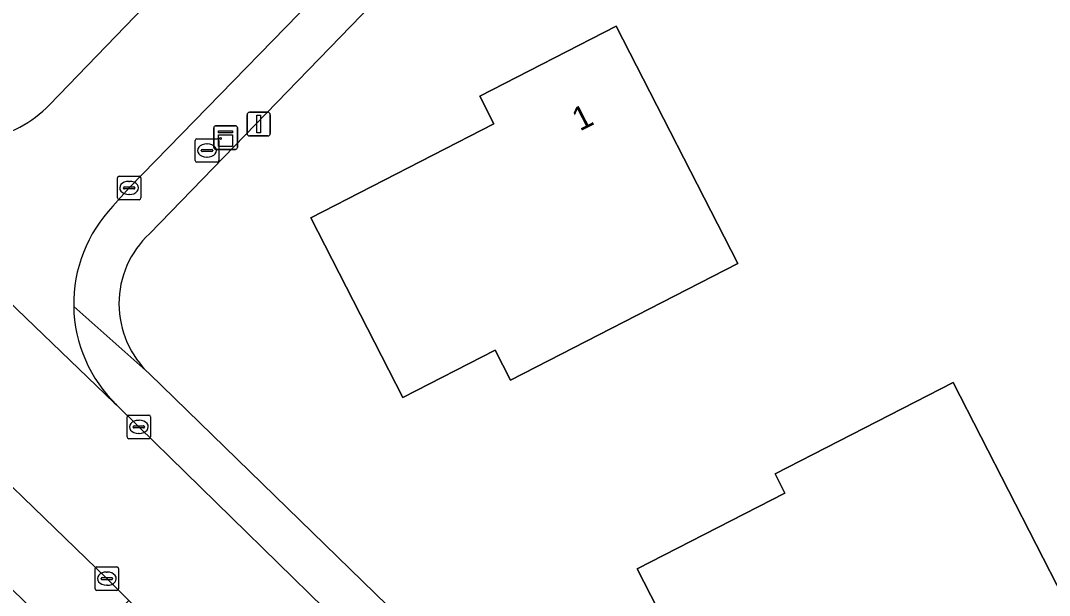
# Model space of a CAD drawing. Extents: x 162722 to 165104, y 384719 to 386284.
# Drawn here: x 163738.67 to 163782.39, y 384905.7 to 384930.12 of the extents above; entities that cross this region are included whole.
import ezdxf

# ---------------------------------------------------------------- set-up
doc = ezdxf.new("R2010")
doc.units = 0
for name, color, linetype in [('IMGEO_Brandkraan', 7, 'Continuous'), ('IMGEO_Erf', 7, 'Continuous'), ('IMGEO_Groenvoorziening', 7, 'Continuous'), ('IMGEO_Kast', 7, 'Continuous'), ('IMGEO_Kolk', 7, 'Continuous'), ('IMGEO_Lichtmast', 7, 'Continuous'), ('IMGEO_Pand', 7, 'Continuous'), ('IMGEO_Pand_nummerreeks', 7, 'Continuous'), ('IMGEO_Parkeervlak_open', 7, 'Continuous'), ('IMGEO_Rijbaan_lokaal_open', 7, 'Continuous')]:
    doc.layers.add(name, color=color, linetype=linetype)

msp = doc.modelspace()

# ---------------------------------------------------------------- linework, layer by layer
at = {"layer": 'IMGEO_Brandkraan'}
for p, q in [((163746.164, 384925.101), (163747.016, 384925.101)), ((163746.089, 384924.175), (163746.089, 384925.027)), ((163746.391, 384924.644), (163746.789, 384924.644)), ((163746.577, 384924.881), (163746.602, 384924.881)), ((163747.09, 384925.027), (163747.09, 384924.175)), ((163746.348, 384924.595), (163746.348, 384924.607)), ((163746.786, 384924.558), (163746.388, 384924.558)), ((163746.6, 384924.321), (163746.575, 384924.321)), ((163746.832, 384924.607), (163746.832, 384924.595)), ((163747.016, 384924.101), (163746.164, 384924.101))]:
    msp.add_line(p, q, dxfattribs=at)
for points in [[(163746.164, 384925.101), (163747.016, 384925.101)], [(163746.089, 384924.175), (163746.089, 384925.027)], [(163747.09, 384925.027), (163747.09, 384924.175)], [(163747.016, 384924.101), (163746.164, 384924.101)]]:
    msp.add_lwpolyline(points, dxfattribs=at)
for centre, radius, start, end in [((163746.166, 384925.025), 0.0765, 91.552, 178.448), ((163746.166, 384925.025), 0.0765, 91.552, 178.448), ((163747.014, 384925.025), 0.0765, 1.552, 88.448), ((163747.014, 384925.025), 0.0765, 1.552, 88.448), ((163746.388, 384924.604), 0.0403, 85.8775, 175.7526), ((163746.793, 384924.606), 0.0386, 1.7309, 96.639), ((163746.385, 384924.594), 0.0366, 178.938, 274.7102), ((163746.789, 384924.601), 0.043, 264.8664, 352.4533), ((163746.166, 384924.177), 0.0765, 181.552, 268.448), ((163746.166, 384924.177), 0.0765, 181.552, 268.448), ((163747.014, 384924.177), 0.0765, 271.552, 358.448), ((163747.014, 384924.177), 0.0765, 271.552, 358.448)]:
    msp.add_arc(centre, radius, start, end, dxfattribs=at)
for centre, major_axis, ratio, start_param, end_param in [((163746.576, 384924.601), (-0.387, 0.002), 0.722429, 4.712389, 7.853982), ((163746.601, 384924.601), (-0.39, 0.002), 0.717154, 1.570796, 4.712389)]:
    msp.add_ellipse(centre, major_axis=major_axis, ratio=ratio, start_param=start_param, end_param=end_param, dxfattribs=at)
at = {"layer": 'IMGEO_Erf'}
for points in [[(163773.478, 384979.9), (163782.291, 384962.358), (163782.404, 384962.416), (163802.16, 384972.581), (163804.226, 384968.418), (163784.518, 384958.283), (163775.869, 384953.781), (163770.816, 384948.556), (163767.966, 384945.654), (163759.567, 384936.98), (163755.864, 384933.157), (163744.141, 384921.063)], [(163739.897, 384926.539), (163750.364, 384937.388), (163772.76, 384960.515)], [(163744.145, 384915.113), (163756.92, 384902.682), (163761.551, 384898.186), (163768.518, 384891.364)]]:
    msp.add_lwpolyline(points, dxfattribs=at)
for points in [[(163759.487, 384914.845), (163758.837, 384916.113), (163754.916, 384914.101), (163750.999, 384921.736), (163758.783, 384925.73), (163758.18, 384926.906), (163763.981, 384929.883), (163769.153, 384919.805)], [(163785.355, 384900.981), (163777.882, 384897.15), (163774.136, 384904.459), (163767.758, 384901.19), (163764.87, 384906.825), (163771.152, 384910.045), (163770.733, 384910.863), (163778.304, 384914.744)]]:
    msp.add_lwpolyline(points, close=True, dxfattribs=at)
for centre, radius, start, end in [((163735.945, 384930.498), 5.594, 282.6076, 314.948), ((163746.913, 384918.09), 4.065, 132.9921, 227.0849)]:
    msp.add_arc(centre, radius, start, end, dxfattribs=at)
at = {"layer": 'IMGEO_Groenvoorziening'}
msp.add_lwpolyline([(163743.27, 384905.487), (163742.334, 384906.411), (163734.773, 384913.719), (163730.72, 384917.677), (163728.529, 384915.354), (163741.103, 384903.254)], close=True, dxfattribs=at)
at = {"layer": 'IMGEO_Kast'}
for p, q in [((163746.88, 384924.723), (163746.88, 384925.564)), ((163746.88, 384925.564), (163746.88, 384924.723)), ((163746.955, 384925.648), (163747.796, 384925.648)), ((163747.796, 384925.648), (163746.955, 384925.648)), ((163747.88, 384925.573), (163747.88, 384924.732)), ((163747.88, 384924.732), (163747.88, 384925.573)), ((163747.805, 384924.648), (163746.964, 384924.648)), ((163746.964, 384924.648), (163747.805, 384924.648))]:
    msp.add_line(p, q, dxfattribs=at)
for points in [[(163747.075, 384925.438), (163747.675, 384925.438), (163747.675, 384925.353), (163747.075, 384925.353), (163747.075, 384925.438)], [(163747.075, 384925.263), (163747.675, 384925.263), (163747.675, 384924.774), (163747.075, 384924.774), (163747.075, 384925.263)]]:
    msp.add_lwpolyline(points, dxfattribs=at)
msp.add_circle((163747.159, 384925.112), 0.0377, dxfattribs=at)
for centre, start, end in [((163746.958, 384925.57), 92.4484, 184.2845), ((163746.958, 384925.57), 92.4484, 184.2845), ((163747.802, 384925.57), 2.4484, 94.2845), ((163747.802, 384925.57), 2.4484, 94.2845), ((163746.958, 384924.726), 182.4484, 274.2845), ((163746.958, 384924.726), 182.4484, 274.2845), ((163747.802, 384924.726), 272.4484, 4.2845), ((163747.802, 384924.726), 272.4484, 4.2845)]:
    msp.add_arc(centre, 0.0779, start, end, dxfattribs=at)
at = {"layer": 'IMGEO_Kolk'}
for p, q in [((163742.779, 384922.585), (163742.779, 384923.437)), ((163742.854, 384923.511), (163743.706, 384923.511)), ((163743.78, 384923.437), (163743.78, 384922.585)), ((163743.038, 384923.005), (163743.038, 384923.017)), ((163743.476, 384922.968), (163743.078, 384922.968)), ((163743.081, 384923.054), (163743.479, 384923.054)), ((163743.267, 384923.291), (163743.292, 384923.291)), ((163743.522, 384923.017), (163743.522, 384923.005)), ((163743.706, 384922.511), (163742.854, 384922.511)), ((163743.29, 384922.731), (163743.265, 384922.731)), ((163743.193, 384912.432), (163743.193, 384913.284)), ((163743.268, 384913.358), (163744.12, 384913.358)), ((163744.194, 384913.284), (163744.194, 384912.432)), ((163743.452, 384912.852), (163743.452, 384912.864)), ((163743.495, 384912.901), (163743.893, 384912.901)), ((163743.681, 384913.138), (163743.706, 384913.138)), ((163743.936, 384912.864), (163743.936, 384912.852)), ((163743.89, 384912.815), (163743.492, 384912.815)), ((163743.704, 384912.578), (163743.679, 384912.578)), ((163744.12, 384912.358), (163743.268, 384912.358)), ((163741.833, 384905.985), (163741.833, 384906.837)), ((163741.908, 384906.911), (163742.76, 384906.911)), ((163742.834, 384906.837), (163742.834, 384905.985)), ((163742.092, 384906.405), (163742.092, 384906.417)), ((163742.53, 384906.368), (163742.132, 384906.368)), ((163742.135, 384906.454), (163742.533, 384906.454)), ((163742.321, 384906.691), (163742.346, 384906.691)), ((163742.576, 384906.417), (163742.576, 384906.405)), ((163742.76, 384905.911), (163741.908, 384905.911)), ((163742.344, 384906.131), (163742.319, 384906.131))]:
    msp.add_line(p, q, dxfattribs=at)
for points in [[(163742.779, 384922.585), (163742.779, 384923.437)], [(163742.854, 384923.511), (163743.706, 384923.511)], [(163743.78, 384923.437), (163743.78, 384922.585)], [(163743.706, 384922.511), (163742.854, 384922.511)], [(163743.193, 384912.432), (163743.193, 384913.284)], [(163743.268, 384913.358), (163744.12, 384913.358)], [(163744.194, 384913.284), (163744.194, 384912.432)], [(163744.12, 384912.358), (163743.268, 384912.358)], [(163741.833, 384905.985), (163741.833, 384906.837)], [(163741.908, 384906.911), (163742.76, 384906.911)], [(163742.834, 384906.837), (163742.834, 384905.985)], [(163742.76, 384905.911), (163741.908, 384905.911)]]:
    msp.add_lwpolyline(points, dxfattribs=at)
for centre, radius, start, end in [((163742.856, 384923.435), 0.0765, 91.552, 178.448), ((163742.856, 384923.435), 0.0765, 91.552, 178.448), ((163743.704, 384923.435), 0.0765, 1.552, 88.448), ((163743.704, 384923.435), 0.0765, 1.552, 88.448), ((163743.078, 384923.014), 0.0403, 85.8775, 175.7526), ((163743.075, 384923.004), 0.0366, 178.938, 274.7102), ((163743.479, 384923.011), 0.043, 264.8664, 352.4533), ((163743.483, 384923.016), 0.0386, 1.7309, 96.639), ((163742.856, 384922.587), 0.0765, 181.552, 268.448), ((163742.856, 384922.587), 0.0765, 181.552, 268.448), ((163743.704, 384922.587), 0.0765, 271.552, 358.448), ((163743.704, 384922.587), 0.0765, 271.552, 358.448), ((163743.27, 384913.282), 0.0765, 91.552, 178.448), ((163743.27, 384913.282), 0.0765, 91.552, 178.448), ((163744.118, 384913.282), 0.0765, 1.552, 88.448), ((163744.118, 384913.282), 0.0765, 1.552, 88.448), ((163743.492, 384912.861), 0.0403, 85.8775, 175.7526), ((163743.489, 384912.851), 0.0366, 178.938, 274.7102), ((163743.893, 384912.858), 0.043, 264.8664, 352.4533), ((163743.897, 384912.863), 0.0386, 1.7309, 96.639), ((163743.27, 384912.434), 0.0765, 181.552, 268.448), ((163743.27, 384912.434), 0.0765, 181.552, 268.448), ((163744.118, 384912.434), 0.0765, 271.552, 358.448), ((163744.118, 384912.434), 0.0765, 271.552, 358.448), ((163741.91, 384906.835), 0.0765, 91.552, 178.448), ((163741.91, 384906.835), 0.0765, 91.552, 178.448), ((163742.758, 384906.835), 0.0765, 1.552, 88.448), ((163742.758, 384906.835), 0.0765, 1.552, 88.448), ((163742.132, 384906.414), 0.0403, 85.8775, 175.7526), ((163742.129, 384906.404), 0.0366, 178.938, 274.7102), ((163742.533, 384906.411), 0.043, 264.8664, 352.4533), ((163742.537, 384906.416), 0.0386, 1.7309, 96.639), ((163741.91, 384905.987), 0.0765, 181.552, 268.448), ((163741.91, 384905.987), 0.0765, 181.552, 268.448), ((163742.758, 384905.987), 0.0765, 271.552, 358.448), ((163742.758, 384905.987), 0.0765, 271.552, 358.448)]:
    msp.add_arc(centre, radius, start, end, dxfattribs=at)
for centre, major_axis, ratio, start_param, end_param in [((163743.266, 384923.011), (-0.387, 0.002), 0.722429, 4.712389, 7.853982), ((163743.291, 384923.011), (-0.39, 0.002), 0.717154, 1.570796, 4.712389), ((163743.68, 384912.858), (-0.387, 0.002), 0.722429, 4.712389, 7.853982), ((163743.705, 384912.858), (-0.39, 0.002), 0.717154, 1.570796, 4.712389), ((163742.32, 384906.411), (-0.387, 0.002), 0.722429, 4.712389, 7.853982), ((163742.345, 384906.411), (-0.39, 0.002), 0.717154, 1.570796, 4.712389)]:
    msp.add_ellipse(centre, major_axis=major_axis, ratio=ratio, start_param=start_param, end_param=end_param, dxfattribs=at)
at = {"layer": 'IMGEO_Lichtmast'}
for p, q in [((163748.29, 384925.324), (163748.29, 384926.124)), ((163748.29, 384926.124), (163748.29, 384925.324)), ((163748.39, 384926.224), (163749.18, 384926.224)), ((163749.18, 384926.224), (163748.39, 384926.224)), ((163749.28, 384926.124), (163749.28, 384925.324)), ((163749.28, 384925.324), (163749.28, 384926.124)), ((163749.18, 384925.224), (163748.39, 384925.224)), ((163748.39, 384925.224), (163749.18, 384925.224))]:
    msp.add_line(p, q, dxfattribs=at)
msp.add_lwpolyline([(163748.71, 384926.099), (163748.86, 384926.099), (163748.86, 384925.349), (163748.71, 384925.349), (163748.71, 384926.099)], dxfattribs=at)
for centre, start, end in [((163748.39, 384926.124), 90, 180), ((163748.39, 384926.124), 90, 180), ((163749.18, 384926.124), 0, 90), ((163749.18, 384926.124), 360, 90), ((163748.39, 384925.324), 180, 270), ((163748.39, 384925.324), 180, 270), ((163749.18, 384925.324), 270, 0), ((163749.18, 384925.324), 270, 0)]:
    msp.add_arc(centre, 0.1, start, end, dxfattribs=at)
at = {"layer": 'IMGEO_Pand'}
for points in [[(163754.916, 384914.101), (163758.837, 384916.113), (163759.487, 384914.845), (163769.153, 384919.805), (163763.981, 384929.883), (163758.18, 384926.906), (163758.783, 384925.73), (163750.999, 384921.736)], [(163785.355, 384900.981), (163778.304, 384914.744), (163770.733, 384910.863), (163771.152, 384910.045), (163764.87, 384906.825), (163767.758, 384901.19), (163774.136, 384904.459), (163777.882, 384897.15)]]:
    msp.add_lwpolyline(points, close=True, dxfattribs=at)
at = {"layer": 'IMGEO_Parkeervlak_open'}
for points in [[(163755.864, 384933.157), (163754.519, 384934.557), (163753.803, 384933.815), (163743.28, 384923.011), (163742.594, 384922.231)], [(163744.141, 384921.063), (163755.864, 384933.157)], [(163744.145, 384915.113), (163744.113, 384915.136), (163740.923, 384917.981)], [(163740.923, 384917.981), (163744.113, 384915.136), (163744.145, 384915.113)], [(163742.747, 384913.794), (163743.694, 384912.858), (163755.5, 384901.311), (163756.92, 384902.682), (163744.145, 384915.113)]]:
    msp.add_lwpolyline(points, dxfattribs=at)
for centre, radius, start, end in [((163746.892, 384918.088), 5.97, 136.0483, 181.0246), ((163746.913, 384918.09), 4.065, 132.9921, 227.0849), ((163746.893, 384918.091), 5.971, 181.0565, 226.0226)]:
    msp.add_arc(centre, radius, start, end, dxfattribs=at)
at = {"layer": 'IMGEO_Rijbaan_lokaal_open'}
for points in [[(163772.76, 384960.515), (163750.364, 384937.388), (163739.897, 384926.539)], [(163742.594, 384922.231), (163743.28, 384923.011), (163753.803, 384933.815), (163754.519, 384934.557), (163758.179, 384938.378), (163763.841, 384944.199)], [(163712.452, 384935.454), (163725.854, 384922.399), (163726.925, 384921.347), (163730.72, 384917.677), (163734.773, 384913.719), (163742.334, 384906.411), (163743.27, 384905.487), (163747.074, 384901.756), (163754.848, 384894.139), (163760.946, 384888.265)], [(163767.038, 384890.055), (163760.158, 384896.76), (163755.5, 384901.311), (163743.694, 384912.858), (163742.747, 384913.794), (163742.638, 384913.882), (163730.224, 384925.82), (163729.987, 384926.103)], [(163729.987, 384926.103), (163730.224, 384925.82), (163742.638, 384913.882), (163742.747, 384913.794)]]:
    msp.add_lwpolyline(points, dxfattribs=at)
for centre, radius, start, end in [((163735.945, 384930.498), 5.594, 282.6076, 314.948), ((163746.892, 384918.088), 5.97, 136.0483, 181.0246), ((163746.893, 384918.091), 5.971, 181.0565, 226.0226)]:
    msp.add_arc(centre, radius, start, end, dxfattribs=at)

# ---------------------------------------------------------------- texts
at = {"layer": 'IMGEO_Pand_nummerreeks'}
msp.add_text('1', height=1, rotation=27.1663, dxfattribs=at).set_placement((163762.435, 384925.402))

doc.saveas('drawing.dxf')
